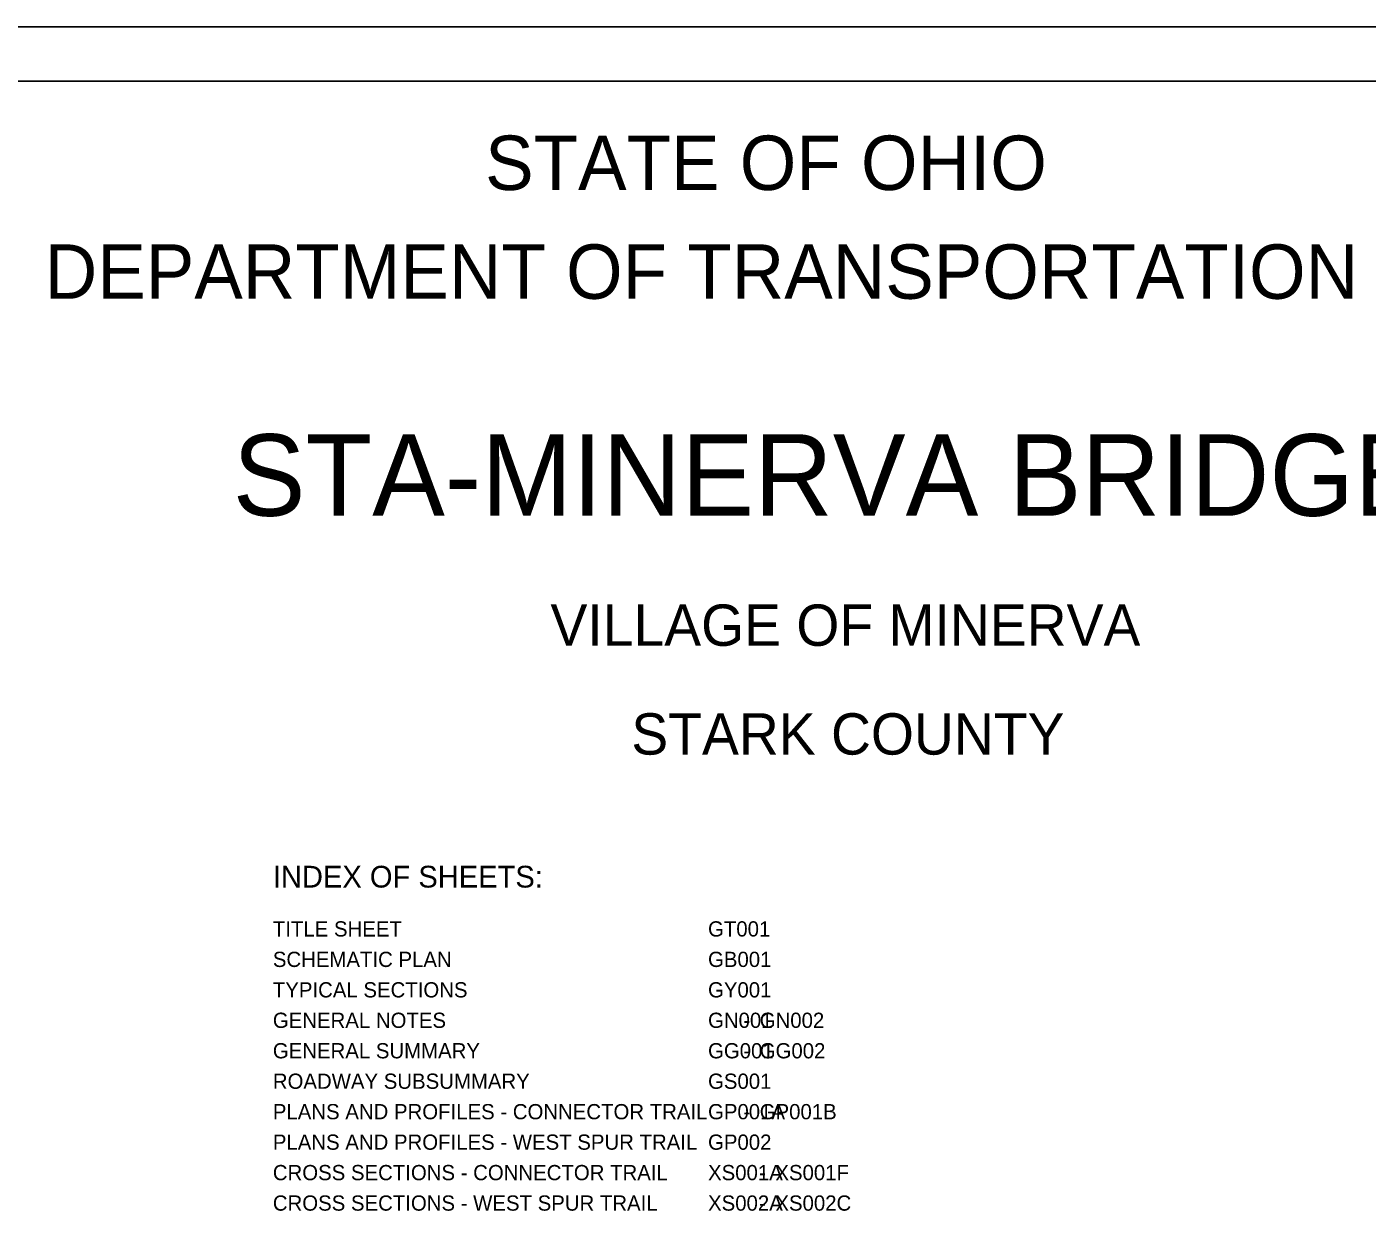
# Model space of a CAD drawing. Extents: x 0 to 34, y 0 to 22.
# Drawn here: x 9.58 to 21.9, y 11.07 to 22 of the extents above; entities that cross this region are included whole.
import ezdxf

# ---------------------------------------------------------------- set-up
doc = ezdxf.new("R2010")
doc.units = 0
for name, color, linetype in [('SH_Border', 7, 'Continuous'), ('SH_Cut_Line', 7, 'Continuous'), ('SH_Text', 7, 'Continuous')]:
    doc.layers.add(name, color=color, linetype=linetype)

msp = doc.modelspace()

# ---------------------------------------------------------------- linework, layer by layer
at = {"layer": 'SH_Border'}
msp.add_lwpolyline([(1.5, 21.5), (33.5, 21.5), (33.5, 0.5), (1.5, 0.5)], close=True, dxfattribs=at)
at = {"layer": 'SH_Cut_Line'}
msp.add_lwpolyline([(0, 0), (34, 0), (34, 22), (0, 22)], close=True, dxfattribs=at)

# ---------------------------------------------------------------- texts
at = {"layer": 'SH_Text'}
for s, height, p in [('STATE OF OHIO', 0.5, (13.795, 20.5)), ('DEPARTMENT OF TRANSPORTATION', 0.5, (9.747, 19.5)), ('STA-MINERVA BRIDGE', 0.75, (11.475, 17.505)), ('VILLAGE OF MINERVA', 0.38, (14.396, 16.31)), ('STARK COUNTY', 0.38, (15.139, 15.31)), ('INDEX OF SHEETS:', 0.2, (11.844, 14.088)), ('TITLE SHEET', 0.14, (11.844, 13.638)), ('GT001', 0.14, (15.844, 13.638)), ('SCHEMATIC PLAN', 0.14, (11.844, 13.358)), ('GB001', 0.14, (15.844, 13.358)), ('TYPICAL SECTIONS', 0.14, (11.844, 13.078)), ('GY001', 0.14, (15.844, 13.078)), ('GENERAL NOTES', 0.14, (11.844, 12.798)), ('GN001', 0.14, (15.844, 12.798)), ('GN002', 0.14, (16.319, 12.798)), ('-', 0.14, (16.169, 12.798)), ('GENERAL SUMMARY', 0.14, (11.844, 12.518)), ('GG001', 0.14, (15.844, 12.518)), ('-', 0.14, (16.169, 12.518)), ('GG002', 0.14, (16.319, 12.518)), ('ROADWAY SUBSUMMARY', 0.14, (11.844, 12.238)), ('GS001', 0.14, (15.844, 12.238)), ('PLANS AND PROFILES - CONNECTOR TRAIL', 0.14, (11.844, 11.958)), ('GP001A', 0.14, (15.844, 11.958)), ('GP001B', 0.14, (16.319, 11.958)), ('-', 0.14, (16.169, 11.958)), ('PLANS AND PROFILES - WEST SPUR TRAIL', 0.14, (11.844, 11.678)), ('GP002', 0.14, (15.844, 11.678)), ('CROSS SECTIONS - CONNECTOR TRAIL', 0.14, (11.844, 11.398)), ('XS001A', 0.14, (15.844, 11.398)), ('-', 0.14, (16.313, 11.398)), ('XS001F', 0.14, (16.463, 11.398)), ('CROSS SECTIONS - WEST SPUR TRAIL', 0.14, (11.844, 11.118)), ('XS002A', 0.14, (15.844, 11.118)), ('XS002C', 0.14, (16.463, 11.118)), ('-', 0.14, (16.313, 11.118))]:
    msp.add_text(s, height=height, dxfattribs=at).set_placement(p)

doc.saveas('drawing.dxf')
